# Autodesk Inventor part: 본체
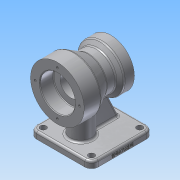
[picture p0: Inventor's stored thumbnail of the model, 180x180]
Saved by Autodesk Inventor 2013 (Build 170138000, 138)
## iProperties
Created: 2019-01
Part Number: 본체
Material: 알루미늄 6061
Document SubType Name: Modeling
Designer: Administrator
Density: 2.71 g/cm^3
Mass: 902.547 g
Surface Area: 602.628 cm^2
Volume: 333.043 cm^3
Author: Administrator
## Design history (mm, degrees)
sketch "스케치1"
  geometry: L1 (-46, -46)-(-46, 46); L2 (-46, 46)-(46, 46); L3 (46, 46)-(46, -46); L4 (46, -46)-(-46, -46); L5 (-46, -46)-(46, 46); L6 (-46, 46)-(46, -46); 1 further point
  constraints: 12 end point, 2 midpoint, 2 parallel, 2 perpendicular, 1 horizontal
  dimensions: "d0" = 92 distance of L1.end L2.end
extrude "돌출1" new body sketch "스케치1" distance "d2" = 10; taper "d3" = 0 deg
fillet "모깎기1" dims "d8" = 10
sketch "스케치3"
  geometry: C1 r 4.5 at (-36, 36); A1 r 10 centre (-36, 36) between (-36, 46) and (-46, 36) reference; 1 further point
  constraints: 1 centre point, 1 coincident
  dimensions: "d9" = 9 diameter of C1
extrude "돌출2" cut sketch "스케치3" stored distance "d11" = 10; taper "d12" = 0 deg
sketch "스케치5"
  geometry: L1 (-46, 36)-(-46, -36) reference; L2 (36, 46)-(-36, 46) reference; C1 r 16 at (-16, 0); 1 further point
  constraints: 1 centre point
  dimensions: "d19" = 46 distance from line of L2 C1.centre; "d20" = 30 distance from line of C1.centre L1; "d22" = 16 radius of C1
sketch "스케치7"
  geometry: L1 (51, 80)-(-29, 80); L2 (-36, 0)-(36, 0) reference; L3 (36, 10)-(-36, 10) reference; L4 (51, 120)-(26, 120); L5 (5.215, 108)-(-8.126, 108); L6 (-8.126, 108)-(-14, 115); L7 (-14, 115)-(-29, 115); L8 (-29, 115)-(-29, 100); L9 (-29, 100)-(-12, 100); L10 (-12, 100)-(-12, 96); L11 (-12, 96)-(31, 96); L12 (31, 96)-(31, 106); L13 (31, 106)-(51, 106); L14 (51, 106)-(51, 120); L15 (5.215, 108)-(26, 120); L16 (46, 10)-(46, 0) reference; 2 further points
  constraints: 26 end point, 8 parallel, 2 vertical alignment, 1 horizontal, 1 midpoint, 1 perpendicular, 1 vertical
  dimensions: "d23" = 80 distance between parallel lines of L2 L1; "d24" = 80 distance of L1.start L1.end; "d25" = 25 distance of L4.start L4.end; "d26" = 15 distance of L6.end L7.end; "d27" = 20 distance of L12.end L13.end; "d28" = 17 distance of L8.end L9.end; "d30" = 40 diameter of L9 L1; "d31" = 32 diameter of L11 L1; "d32" = 52 diameter of L13 L1; "d33" = 80 diameter of L4 L1; "d34" = 70 diameter of L7 L1; "d37" = 50 deg angle of L5 L6; "d38" = 30 deg angle of L5 L15; "d39" = 56 diameter of L5 L1; "d44" = 5 distance from line of L16 L1.start
revolve "회전1" sketch "스케치7" stored, may be unused: angle "d40" = 90 deg
extrude "돌출3" join sketch "스케치5" stored distance "d41" = 10; taper "d42" = 0 deg
sketch "스케치11"
  geometry: L1 (-36, -46)-(36, -46) reference; L2 (46, -36)-(46, 36) reference; L3 (36, -5)-(-0.801, -5); L4 (-0.801, -5)-(-0.801, 5); L5 (-0.801, 5)-(36, 5); L6 (36, 5)-(36, -5); L7 (36, -5)-(-0.801, 5); L8 (-0.801, -5)-(36, 5); A1 r 16 centre (-16, 0) between (0, 0) and (-0.801, 5) reference; 2 further points
  constraints: 12 end point, 3 midpoint, 3 parallel, 1 horizontal alignment, 1 perpendicular, 1 point on circle
  dimensions: "d51" = 10 distance between parallel lines of L2 L6; "d52" = 10 distance of L5.end L3.start
extrude "돌출4" join sketch "스케치11" stored distance "d53" = 10; taper "d54" = 0 deg
feature "면 기울기1" dims angle "d55" = 25 deg
fillet "모깎기2" dims "d56" = 0.6
fillet "모깎기3" dims "d57" = 1
fillet "모깎기4" dims "d58" = 3
fillet "모깎기5" dims "d59" = 3
fillet "모깎기6" dims "d60" = 3
fillet "모깎기7" dims "d61" = 3
sketch "스케치12" dims "d63" = 66
  geometry: L1 (-80, -36)-(-80, 36) reference; C1 r 40 at (0, 0) reference; 4 further points
  constraints: 2 horizontal alignment, 1 coincident, 1 midpoint, 2 other
hole "구멍1" sketch "스케치12" at (33, 0) diameter "d65" = 3.242; stored, may be unused: countersink angle "d69" = 90 deg, drill point angle "d71" = 118 deg; dims "d66" = 9, "d67" = 4, "d68" = 2, "d70" = 11
sketch "스케치13" dims "d75" = 55
  geometry: C1 r 35 at (0, 0) reference; C2 r 20 at (0, 0) reference; 3 further points
  constraints: 2 horizontal alignment, 1 coincident, 2 other
hole "구멍2" sketch "스케치13" at (27.5, 0) diameter "d77" = 3.242; stored, may be unused: countersink angle "d81" = 90 deg, drill point angle "d83" = 118 deg; dims "d78" = 9, "d79" = 4, "d80" = 2, "d82" = 11
fillet "모깎기8" dims "d87" = 3
sketch "스케치14"
  geometry: L1 (72, 0)-(0, 0) reference; L2 (-10, 7)-(-10, 0) reference; 2 further points
  constraints: 1 other
  dimensions: "d88" = 46 distance from line of point (36, 4) L2; "d89" = 4 distance from line of L1 point (36, 4)
feature "엠보싱1" sketch "스케치14" dims "d0" = 92, "d90" = 0.5, "d91" = 0
chamfer "모따기1" distance "d92" = 1; stored, may be unused: second distance "d93" = 2, angle "d94" = 45 deg
node "솔리드1"
pattern_linear "직사각형 패턴1" dims "d15" = 72, "d18" = 72
pattern_circular "원형 패턴1" dims angle "d73" = 360 deg
pattern_circular "원형 패턴2" dims angle "d85" = 360 deg
